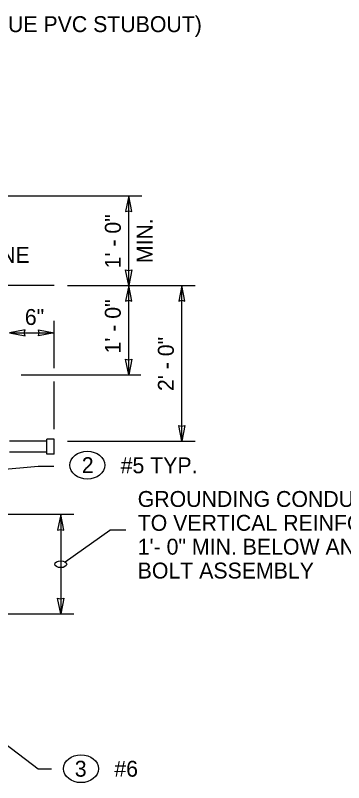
# Model space of a CAD drawing. Extents: x 99862 to 104211, y 98939 to 105076.
# Drawn here: x 101234 to 101564, y 100707 to 101479 of the extents above; entities that cross this region are included whole.
import ezdxf

# ---------------------------------------------------------------- set-up
doc = ezdxf.new("R2010")
doc.units = 0
for name, color, linetype in [('Level 15', 7, 'Continuous'), ('Level 20', 7, 'Continuous'), ('Level 5', 7, 'Continuous'), ('Level 7', 7, 'Continuous'), ('Level 9', 7, 'Continuous')]:
    doc.layers.add(name, color=color, linetype=linetype)

msp = doc.modelspace()

# ---------------------------------------------------------------- linework, layer by layer
at = {"layer": 'Level 15'}
for p, q in [((100948.61, 101297.4), (101361.11, 101297.4)), ((101347.78, 101207.4), (101347.78, 101297.4)), ((101286.11, 101207.4), (101414.44, 101207.4)), ((101347.78, 101117.4), (101347.78, 101207.4)), ((101401.11, 101050.74), (101401.11, 101207.4)), ((101272.78, 101124.07), (101272.78, 101171.6)), ((101227.78, 101159.6), (101272.78, 101159.6)), ((101239.78, 101117.4), (101359.78, 101117.4)), ((101272.78, 101062.74), (101272.78, 101110.74)), ((101286.11, 101050.74), (101414.44, 101050.74)), ((101111.57, 101012.66), (101256.7, 101025.61)), ((101256.7, 101025.61), (101272.37, 101025.61)), ((101292.71, 100976.97), (100905.73, 100976.97)), ((101279.38, 100976.97), (101279.38, 100876.97)), ((101283.96, 100929.2), (101328.8, 100961.2)), ((100747.61, 100876.97), (101292.71, 100876.97)), ((101208.03, 100758.12), (101256.81, 100721.22)), ((101256.81, 100721.22), (101270.27, 100721.22))]:
    msp.add_line(p, q, dxfattribs=at)
msp.add_ellipse((101279.38, 100926.97), major_axis=(-6, 0), ratio=0.57735, dxfattribs=at)
at = {"layer": 'Level 20'}
for centre in [(101306.15, 101026.57), (101299.77, 100721.22)]:
    msp.add_ellipse(centre, major_axis=(-17.5, 0), ratio=0.8, dxfattribs=at)
at = {"layer": 'Level 5'}
for p, q in [((101265.28, 101050.74), (101227.78, 101050.74)), ((101272.78, 101052.61), (101265.28, 101052.61)), ((101265.28, 101037.61), (101265.28, 101052.61)), ((101272.78, 101037.61), (101272.78, 101052.61)), ((101265.28, 101039.49), (101227.78, 101039.49)), ((101272.78, 101037.61), (101265.28, 101037.61))]:
    msp.add_line(p, q, dxfattribs=at)
at = {"layer": 'Level 7'}
msp.add_line((101344.8, 100961.2), (101328.8, 100961.2), dxfattribs=at)
for points in [[(101347.78, 101297.4), (101344.69, 101281.68), (101347.78, 101282.41), (101350.86, 101281.68)], [(101347.78, 101207.4), (101344.69, 101223.13), (101347.78, 101222.4), (101350.86, 101223.13)], [(101347.78, 101207.4), (101344.69, 101191.68), (101347.78, 101192.41), (101350.86, 101191.68)], [(101401.11, 101207.4), (101398.03, 101191.68), (101401.11, 101192.41), (101404.19, 101191.68)], [(101227.78, 101159.6), (101243.5, 101156.51), (101242.77, 101159.6), (101243.5, 101162.68)], [(101272.78, 101159.6), (101257.05, 101156.51), (101257.78, 101159.6), (101257.05, 101162.68)], [(101347.78, 101117.4), (101344.69, 101133.13), (101347.78, 101132.4), (101350.86, 101133.13)], [(101401.11, 101050.74), (101398.03, 101066.46), (101401.11, 101065.73), (101404.19, 101066.46)], [(101279.38, 100976.97), (101276.3, 100961.24), (101279.38, 100961.97), (101282.47, 100961.24)], [(101279.38, 100876.97), (101276.3, 100892.69), (101279.38, 100891.96), (101282.47, 100892.69)]]:
    msp.add_lwpolyline(points, close=True, dxfattribs=at)
at = {"layer": 'Level 9'}
msp.add_line((101272.78, 101207.4), (100935.28, 101207.4), dxfattribs=at)

# ---------------------------------------------------------------- texts
at = {"layer": 'Level 20'}
for s, rotation, p in [('OF FOUNDATION (DO NOT GLUE PVC STUBOUT)', 360, (100918.51, 101462.17)), ('1\' - 0"', 90, (101339.78, 101224.47)), ('MIN.', 90, (101371.78, 101229.79)), ('FINISH GROUND LINE', 0.0239, (101023.56, 101229.95)), ('1\' - 0"', 90, (101339.78, 101138.87)), ('2\' - 0"', 90, (101393.11, 101101.14))]:
    msp.add_text(s, height=16, rotation=rotation, dxfattribs=at).set_placement(p)
for s, p in [('6"', (101243.3, 101167.6)), ('2', (101300.61, 101018.57)), ('#5 TYP.', (101339.65, 101018.41)), ('GROUNDING CONDUCTOR TO ATTACH ', (101356.8, 100984.56)), ('TO VERTICAL REINFORCING STEEL ', (101356.8, 100960.56)), ('1\'- 0" MIN. BELOW ANCHOR ', (101356.8, 100936.56)), ('BOLT ASSEMBLY', (101356.8, 100912.56)), ('3', (101293.51, 100713.22)), ('#6', (101333.27, 100713.22))]:
    msp.add_text(s, height=16, dxfattribs=at).set_placement(p)

doc.saveas('drawing.dxf')
